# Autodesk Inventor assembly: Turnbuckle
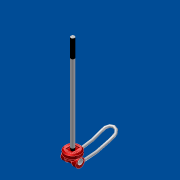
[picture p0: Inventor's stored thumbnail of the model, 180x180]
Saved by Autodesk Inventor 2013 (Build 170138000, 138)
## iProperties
Shininess: 20.0
Length Units: 11269
Angle Units: 11279
Time Units: 11290
Mass Units: 11283
Length Display Precision: 3
Angle Display Precision: 2
Created: 2001-04
Part Number: Turnbuckle
Document SubType Name: Baugruppe
Designer: dl
Density: 0.0
Volumn: 0.0
Area: 0.0
PropertySet Name: Model Information
Control State: 0
Master: False
Checked Out: False
Author: dl
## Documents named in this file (8)
- C:\Webworld\Webworld2014\ATC2013\Assemblies\ATC-Baby Carriage\3-FRONT WHEEL\Turnbuckle.iam
- C:\Webworld\Webworld2014\ATC2013\Assemblies\ATC-Baby Carriage\3-FRONT WHEEL\Wire_leverl.ipt
- C:\Webworld\Webworld2014\ATC2013\Assemblies\ATC-Baby Carriage\3-FRONT WHEEL\Cam.ipt
- C:\Webworld\Webworld2014\ATC2013\Assemblies\ATC-Baby Carriage\3-FRONT WHEEL\Beam.ipt
- C:\Webworld\Webworld2014\ATC2013\Assemblies\ATC-Baby Carriage\3-FRONT WHEEL\Terminal_washer.ipt
- C:\Webworld\Webworld2014\ATC2013\Assemblies\ATC-Baby Carriage\3-FRONT WHEEL\Bolt_turnbuckle.ipt
- C:\Webworld\Webworld2014\ATC2013\Assemblies\ATC-Baby Carriage\3-FRONT WHEEL\Lock_washer.ipt
- C:\Webworld\Webworld2014\ATC2013\Assemblies\ATC-Baby Carriage\3-FRONT WHEEL\Tension_axle.ipt
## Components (8 placed, 7 different names)
1. Beam:1 — Insert:1, Mate:2, Mate:4
2. Wire_leverl:1 — Insert:2, Insert:3, Angle:1
3. Cam:1 — Insert:1, Mate:1, Insert:2, Mate:5
4. Cam:2 — Mate:1, Insert:3, Mate:5, Tangent:1, Angle:2
5. Terminal_washer:1 — Mate:2, Mate:3, Tangent:1, Angle:2
6. Bolt_turnbuckle:1 — Insert:4
7. Lock_washer:1 — Insert:4
8. Tension_axle:1 — Mate:3, Mate:4, Angle:1
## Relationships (12: Mate 5, Insert 4, Angle 2, Tangent 1)
- Insert:1: Beam:1 ↔ Cam:1
- Mate:1: Cam:1 ↔ Cam:2
- Insert:2: Wire_leverl:1 ↔ Cam:1
- Insert:3: Wire_leverl:1 ↔ Cam:2
- Mate:2: Beam:1 ↔ Terminal_washer:1
- Insert:4: Bolt_turnbuckle:1 ↔ Lock_washer:1
- Mate:3: Terminal_washer:1 ↔ Tension_axle:1
- Mate:4: Beam:1 ↔ Tension_axle:1
- Mate:5: Cam:1 ↔ Cam:2
- Angle:1: Wire_leverl:1 ↔ Tension_axle:1
- Tangent:1: Cam:2 ↔ Terminal_washer:1
- Angle:2: Cam:2 ↔ Terminal_washer:1
